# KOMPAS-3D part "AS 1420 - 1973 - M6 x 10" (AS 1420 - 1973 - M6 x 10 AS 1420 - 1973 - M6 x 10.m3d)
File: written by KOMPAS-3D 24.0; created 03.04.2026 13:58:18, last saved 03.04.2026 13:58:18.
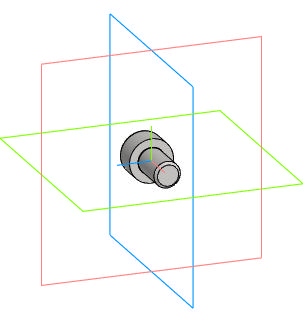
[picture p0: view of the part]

Document properties: Автор: R2D2; Полное имя файла: E:\Работа\Зайцев\Аксессуары для пневмоприводов\Ручной дублер DN.ru\MON2-450-T28-ISO Ручной дублер DN.ru\исходные материалы\AS 1420 - 1973 - M6 x 10 AS 1420 - 1973 - M6 x 10.m3d

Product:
- Body: Solid1  | qty 1
- Part/product: AS 1420 - 1973 - M6 x 10
    Комментарий: Винты с шестигранным   углублением метрические   ISO
    additional columns: Сталь, мягкая

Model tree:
1. Solid1  (labels: Solid1)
